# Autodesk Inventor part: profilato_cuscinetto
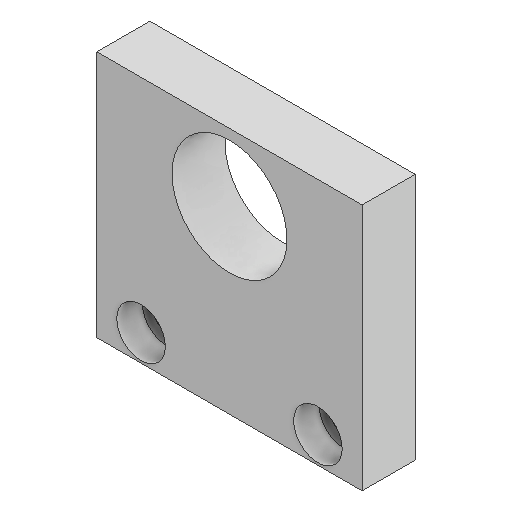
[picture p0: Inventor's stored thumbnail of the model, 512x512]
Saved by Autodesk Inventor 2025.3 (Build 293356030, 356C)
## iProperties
Created: 2025-11
Part Number: profilato_cuscinetto
Material: Generico
Document SubType Name: Modeling
Designer: R5800u
Density: 1 g/cm^3
Appearance: Default
Author: R5800u
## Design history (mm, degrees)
feature "Base2"
sketch "Schizzo1"
  geometry: L1 (0, 0)-(0, 5.7) reference; L2 (0, 0)-(30, 0) reference; L3 (30, 5.7)-(30, 0) reference; L4 (0, 5.7)-(30, 5.7) reference; C1 r 1.45 at (25, 3) reference; C2 r 1.45 at (5, 3) reference; 1 further point
extrude "Estrusione1" join sketch "Schizzo1" stored distance "d0" = 10; taper "d1" = 0 deg
node "Solido1"
node "Solido2"
node "Linea chiusa proiettata1"
